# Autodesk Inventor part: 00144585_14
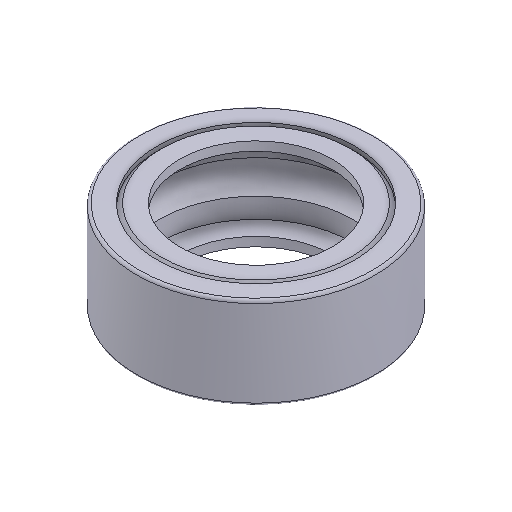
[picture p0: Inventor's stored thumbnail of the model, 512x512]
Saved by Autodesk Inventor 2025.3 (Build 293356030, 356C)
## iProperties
Created: 2021-02
Part Number: 00144585_14
Material: Generico
Document SubType Name: Modeling
Designer: R5800u
Density: 1 g/cm^3
Appearance: Default
Author: TraceParts
Sending System: SolidWorks 2021
Last Author: Albert
Last Saved: 2021-07-28
IsFastener: 1
TYPE: CATASM
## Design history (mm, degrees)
feature "Imported1"
node "Solido1"
